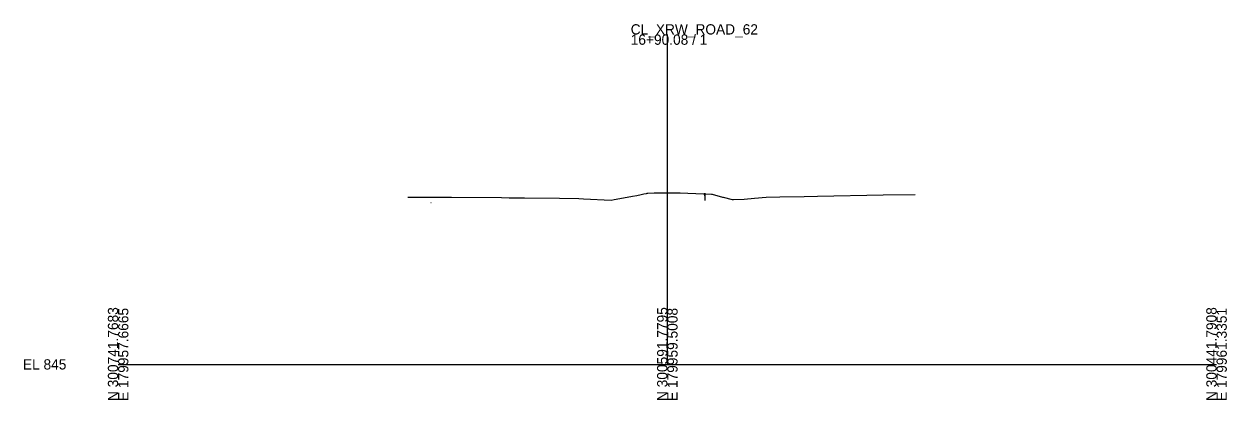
# Model space of a CAD drawing. Extents: x -26 to 303, y 490 to 4093.
# Drawn here: x -25.7 to 302.8, y 1490.3 to 1592.8 of the extents above; entities that cross this region are included whole.
import ezdxf

# ---------------------------------------------------------------- set-up
doc = ezdxf.new("R2010")
doc.units = 0
for name, color, linetype in [('CM_Corridor_Bottom_Mesh', 7, 'Continuous'), ('Default', 7, 'Continuous'), ('GK_Cells', 7, 'Continuous'), ('MD_P_Surface_Aggregate_Base', 7, 'Continuous'), ('MD_P_Surface_Asphalt_Concrete_Base', 7, 'Continuous'), ('MD_P_Surface_Asphalt_Concrete_Surface_Course', 7, 'Continuous'), ('MD_P_Surface_Chemically_Stabalized_Subgrade', 7, 'Continuous'), ('VG_X_Text', 7, 'Continuous'), ('XS_X_Ground_Line', 7, 'Continuous')]:
    doc.layers.add(name, color=color, linetype=linetype)

msp = doc.modelspace()

# ---------------------------------------------------------------- linework, layer by layer
at = {"layer": 'CM_Corridor_Bottom_Mesh'}
msp.add_lwpolyline([(160.24, 1546.01), (160.24, 1546.68)], dxfattribs=at)
at = {"layer": 'GK_Cells'}
for p, q in [((150, 1500), (150, 1590)), ((0, 1500), (150, 1500)), ((150, 1500), (300, 1500))]:
    msp.add_line(p, q, dxfattribs=at)
at = {"layer": 'MD_P_Surface_Aggregate_Base'}
for points in [[(160.24, 1546.01), (160.24, 1546.68)], [(160.24, 1546.24), (160.24, 1545.74)]]:
    msp.add_lwpolyline(points, dxfattribs=at)
at = {"layer": 'MD_P_Surface_Asphalt_Concrete_Base'}
msp.add_lwpolyline([(160.24, 1546.58), (160.24, 1546.24)], dxfattribs=at)
at = {"layer": 'MD_P_Surface_Asphalt_Concrete_Surface_Course'}
msp.add_lwpolyline([(160.24, 1546.68), (160.24, 1546.58)], dxfattribs=at)
at = {"layer": 'MD_P_Surface_Chemically_Stabalized_Subgrade'}
msp.add_lwpolyline([(160.24, 1545.74), (160.24, 1544.74)], dxfattribs=at)
at = {"layer": 'VG_X_Text'}
msp.add_lwpolyline([(85.53, 1544.04), (85.41, 1544.04)], dxfattribs=at)
msp.add_lwpolyline([(85.53, 1544.04), (85.41, 1544.04)], dxfattribs=at)
at = {"layer": 'XS_X_Ground_Line'}
msp.add_lwpolyline([(79.13, 1545.6), (80.95, 1545.6), (91.06, 1545.65), (104.73, 1545.5), (106.76, 1545.46), (111.01, 1545.41), (120.55, 1545.31), (125.86, 1545.26), (127.14, 1545.2), (134.67, 1544.84), (135.5, 1544.97), (140, 1545.76), (140.44, 1545.85), (141.69, 1546.11), (142.88, 1546.35), (143.61, 1546.5), (144.31, 1546.66), (144.48, 1546.7), (144.7, 1546.71), (146.41, 1546.76), (152.5, 1546.78), (153.51, 1546.78), (159.86, 1546.52), (160.24, 1546.5), (162.06, 1546.46), (162.13, 1546.46), (162.25, 1546.43), (165.04, 1545.66), (165.23, 1545.61), (167.73, 1545.01), (168.05, 1545.02), (171.02, 1545.11), (173.77, 1545.33), (176.95, 1545.6), (180.76, 1545.67), (187.41, 1545.79), (191.02, 1545.85), (208.96, 1546.25), (217.71, 1546.33)], dxfattribs=at)

# ---------------------------------------------------------------- texts
at = {"layer": 'Default'}
msp.add_text('-', height=0.0001, dxfattribs=at).set_placement((0, 1500))
at = {"layer": 'GK_Cells'}
for s, p in [('CL_XRW_ROAD_62', (140, 1590)), ('16+90.08 / 1', (140, 1587.2)), ('EL 845', (-26, 1498.6))]:
    msp.add_text(s, height=2.8, dxfattribs=at).set_placement(p)
for s, p in [('N 300741.7683', (0, 1490)), ('E 179957.6665', (2.8, 1490)), ('N 300591.7795', (150, 1490)), ('E 179959.5008', (152.8, 1490)), ('N 300441.7908', (300, 1490)), ('E 179961.3351', (302.8, 1490))]:
    msp.add_text(s, height=2.8, rotation=90, dxfattribs=at).set_placement(p)

doc.saveas('drawing.dxf')
